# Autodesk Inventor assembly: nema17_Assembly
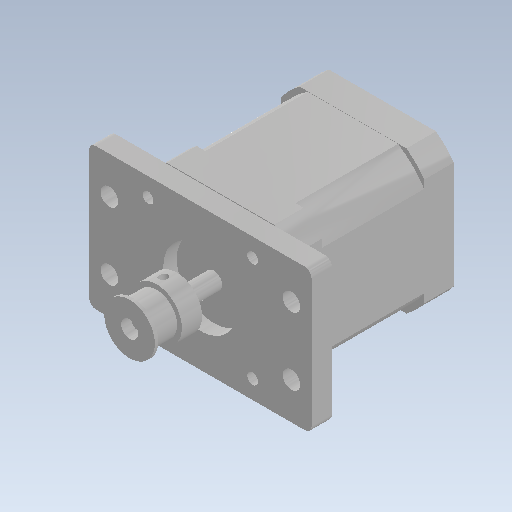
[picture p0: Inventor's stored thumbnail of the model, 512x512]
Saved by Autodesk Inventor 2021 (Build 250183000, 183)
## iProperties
Created: 2026-10
Part Number: nema17_Assembly
Document SubType Name: Assembly
Designer: hp
Author: hp
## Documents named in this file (4)
- C:\Users\hp\Downloads\nema17_Assembly.iam
- C:\Users\hp\Downloads\Nema_17_Mount.ipt
- C:\Users\hp\Downloads\Nema 17 Stepper Motor_1.ipt
- C:\Users\hp\Downloads\GT2 Timing Pulley 20 Tooth_5mm.ipt
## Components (3 placed, 3 different names)
1. Nema_17_Mount:1
2. Nema 17 Stepper Motor:1
3. GT2 Timing Pulley 20 Tooth_5mm:1
